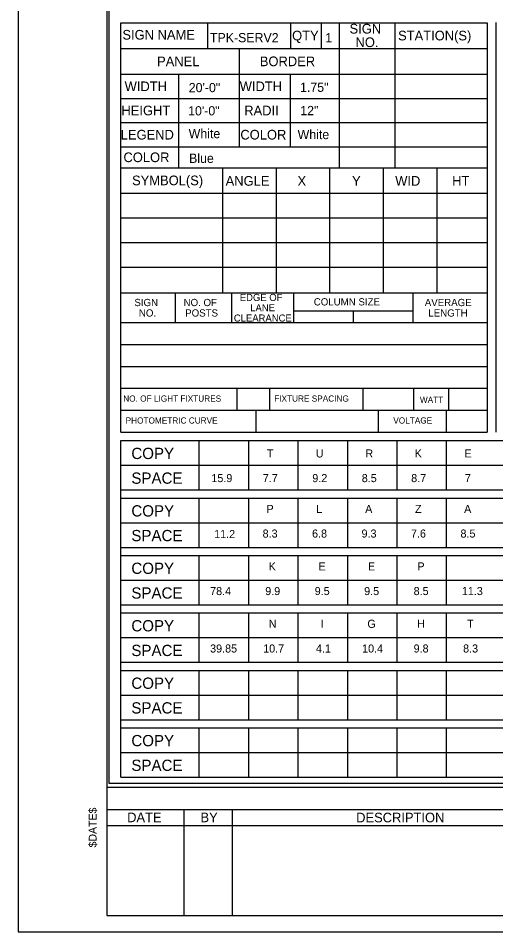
# Model space of a CAD drawing. Extents: x 17890071 to 17890754, y 17897628 to 17897992.
# Drawn here: x 17890071.1 to 17890100.2, y 17897766.7 to 17897822.3 of the extents above; entities that cross this region are included whole.
import ezdxf

# ---------------------------------------------------------------- set-up
doc = ezdxf.new("R2010")
doc.units = 0
for name, color, linetype in [('GSSign', 7, 'Continuous'), ('PlotBorder_dp', 7, 'Continuous'), ('SheetBorder_dp', 7, 'Continuous'), ('SheetLines_dp', 7, 'Continuous'), ('SheetLinesMisc1_dp', 7, 'Continuous'), ('SheetLinesMisc2_dp', 7, 'Continuous'), ('TextMinor', 7, 'Continuous'), ('TextMisc', 7, 'Continuous')]:
    doc.layers.add(name, color=color, linetype=linetype)

msp = doc.modelspace()

# ---------------------------------------------------------------- linework, layer by layer
at = {"layer": 'PlotBorder_dp'}
msp.add_lwpolyline([(17890071.13, 17897766.734), (17890232.646, 17897766.734), (17890232.646, 17897870.495), (17890071.13, 17897870.495)], close=True, dxfattribs=at)
at = {"layer": 'SheetBorder_dp'}
for p, q in [((17890076.514, 17897869.516), (17890076.514, 17897767.712)), ((17890076.514, 17897775.543), (17890227.262, 17897775.543)), ((17890076.514, 17897767.712), (17890227.262, 17897767.712))]:
    msp.add_line(p, q, dxfattribs=at)
at = {"layer": 'SheetLines_dp'}
for p, q in [((17890076.514, 17897774.173), (17890132.897, 17897774.173)), ((17890081.212, 17897774.173), (17890081.212, 17897767.712)), ((17890084.149, 17897774.173), (17890084.149, 17897767.712)), ((17890076.514, 17897773.194), (17890132.897, 17897773.194))]:
    msp.add_line(p, q, dxfattribs=at)
at = {"layer": 'SheetLinesMisc1_dp'}
for p, q in [((17890082.658, 17897820.501), (17890082.658, 17897822.069)), ((17890087.705, 17897822.069), (17890087.705, 17897820.501)), ((17890089.558, 17897822.069), (17890089.558, 17897820.501)), ((17890090.662, 17897822.069), (17890090.662, 17897813.235)), ((17890094.057, 17897822.069), (17890094.057, 17897813.235)), ((17890077.364, 17897820.501), (17890099.675, 17897820.501)), ((17890084.575, 17897820.501), (17890084.575, 17897814.499)), ((17890077.364, 17897818.932), (17890099.675, 17897818.932)), ((17890080.89, 17897818.932), (17890080.89, 17897813.235)), ((17890087.686, 17897818.917), (17890087.686, 17897814.499)), ((17890077.364, 17897817.46), (17890099.675, 17897817.46)), ((17890077.364, 17897815.988), (17890099.675, 17897815.988)), ((17890077.364, 17897814.515), (17890099.675, 17897814.515)), ((17890077.364, 17897813.235), (17890099.675, 17897813.235)), ((17890083.56, 17897813.235), (17890083.56, 17897805.616)), ((17890086.82, 17897813.235), (17890086.82, 17897805.616)), ((17890090.08, 17897813.235), (17890090.08, 17897805.616)), ((17890093.34, 17897813.206), (17890093.34, 17897805.616)), ((17890096.6, 17897813.206), (17890096.6, 17897805.616)), ((17890077.369, 17897811.702), (17890099.675, 17897811.702)), ((17890077.369, 17897810.199), (17890099.675, 17897810.199)), ((17890077.369, 17897808.695), (17890099.675, 17897808.695)), ((17890077.369, 17897807.192), (17890099.675, 17897807.192)), ((17890077.364, 17897805.616), (17890099.675, 17897805.616)), ((17890080.675, 17897805.616), (17890080.675, 17897803.819)), ((17890084.097, 17897805.616), (17890084.097, 17897803.819)), ((17890087.875, 17897805.616), (17890087.875, 17897803.819)), ((17890095.151, 17897805.616), (17890095.151, 17897803.819)), ((17890087.875, 17897804.538), (17890095.146, 17897804.538)), ((17890091.511, 17897804.538), (17890091.511, 17897803.819)), ((17890077.364, 17897803.819), (17890099.675, 17897803.819)), ((17890077.364, 17897802.484), (17890099.675, 17897802.484)), ((17890077.364, 17897801.148), (17890099.675, 17897801.148)), ((17890077.364, 17897799.813), (17890099.675, 17897799.813)), ((17890077.364, 17897798.477), (17890099.675, 17897798.477))]:
    msp.add_line(p, q, dxfattribs=at)
at = {"layer": 'SheetLinesMisc2_dp'}
for p, q in [((17890076.643, 17897869.435), (17890076.643, 17897775.777)), ((17890077.364, 17897797.141), (17890077.364, 17897822.069)), ((17890077.364, 17897822.069), (17890099.675, 17897822.069)), ((17890099.675, 17897822.069), (17890099.675, 17897797.141)), ((17890100.188, 17897822.071), (17890100.188, 17897797.179)), ((17890077.364, 17897799.812), (17890099.67, 17897799.812)), ((17890084.422, 17897799.812), (17890084.422, 17897798.477)), ((17890086.415, 17897799.812), (17890086.415, 17897798.477)), ((17890092.09, 17897799.812), (17890092.09, 17897798.477)), ((17890095.177, 17897799.812), (17890095.177, 17897798.477)), ((17890097.306, 17897799.812), (17890097.306, 17897798.477)), ((17890077.364, 17897798.477), (17890099.67, 17897798.477)), ((17890085.592, 17897798.477), (17890085.592, 17897797.141)), ((17890093.035, 17897798.477), (17890093.035, 17897797.141)), ((17890097.177, 17897798.477), (17890097.177, 17897797.141)), ((17890077.364, 17897797.141), (17890099.67, 17897797.141)), ((17890077.364, 17897797.141), (17890099.675, 17897797.141)), ((17890100.188, 17897797.179), (17890100.188, 17897797.146)), ((17890077.364, 17897796.631), (17890151.359, 17897796.631)), ((17890077.364, 17897776.142), (17890077.364, 17897796.631)), ((17890082.127, 17897796.631), (17890082.127, 17897793.624)), ((17890085.138, 17897796.631), (17890085.138, 17897793.624)), ((17890088.148, 17897796.631), (17890088.148, 17897793.624)), ((17890091.158, 17897796.631), (17890091.158, 17897793.624)), ((17890094.168, 17897796.631), (17890094.168, 17897793.624)), ((17890097.177, 17897796.631), (17890097.177, 17897793.624)), ((17890077.364, 17897795.129), (17890151.359, 17897795.129)), ((17890077.364, 17897793.624), (17890151.359, 17897793.624)), ((17890077.364, 17897793.134), (17890151.359, 17897793.134)), ((17890082.127, 17897793.134), (17890082.127, 17897790.128)), ((17890085.138, 17897793.134), (17890085.138, 17897790.128)), ((17890088.148, 17897793.134), (17890088.148, 17897790.128)), ((17890091.158, 17897793.134), (17890091.158, 17897790.128)), ((17890094.168, 17897793.134), (17890094.168, 17897790.128)), ((17890097.177, 17897793.134), (17890097.177, 17897790.128)), ((17890077.364, 17897791.631), (17890151.359, 17897791.631)), ((17890077.364, 17897790.128), (17890151.359, 17897790.128)), ((17890077.364, 17897789.637), (17890151.359, 17897789.637)), ((17890082.127, 17897789.637), (17890082.127, 17897786.631)), ((17890085.138, 17897789.637), (17890085.138, 17897786.631)), ((17890088.148, 17897789.637), (17890088.148, 17897786.631)), ((17890091.158, 17897789.637), (17890091.158, 17897786.631)), ((17890094.168, 17897789.637), (17890094.168, 17897786.631)), ((17890097.177, 17897789.637), (17890097.177, 17897786.631)), ((17890077.364, 17897788.135), (17890151.359, 17897788.135)), ((17890077.364, 17897786.631), (17890151.359, 17897786.631)), ((17890077.364, 17897786.141), (17890151.359, 17897786.141)), ((17890082.127, 17897786.141), (17890082.127, 17897783.135)), ((17890085.138, 17897786.141), (17890085.138, 17897783.135)), ((17890088.148, 17897786.141), (17890088.148, 17897783.135)), ((17890091.158, 17897786.141), (17890091.158, 17897783.135)), ((17890094.168, 17897786.141), (17890094.168, 17897783.135)), ((17890097.177, 17897786.141), (17890097.177, 17897783.135)), ((17890077.364, 17897784.639), (17890151.359, 17897784.639)), ((17890077.364, 17897783.135), (17890151.359, 17897783.135)), ((17890077.364, 17897782.644), (17890151.359, 17897782.644)), ((17890082.127, 17897782.644), (17890082.127, 17897779.638)), ((17890085.138, 17897782.644), (17890085.138, 17897779.638)), ((17890088.148, 17897782.644), (17890088.148, 17897779.638)), ((17890091.158, 17897782.644), (17890091.158, 17897779.638)), ((17890094.168, 17897782.644), (17890094.168, 17897779.638)), ((17890097.177, 17897782.644), (17890097.177, 17897779.638)), ((17890077.364, 17897781.141), (17890151.359, 17897781.141)), ((17890077.364, 17897779.638), (17890151.359, 17897779.638)), ((17890077.364, 17897779.148), (17890151.359, 17897779.148)), ((17890082.127, 17897779.148), (17890082.127, 17897776.142)), ((17890085.138, 17897779.148), (17890085.138, 17897776.142)), ((17890088.148, 17897779.148), (17890088.148, 17897776.142)), ((17890091.158, 17897779.148), (17890091.158, 17897776.142)), ((17890094.168, 17897779.148), (17890094.168, 17897776.142)), ((17890097.177, 17897779.148), (17890097.177, 17897776.142)), ((17890077.364, 17897777.645), (17890151.359, 17897777.645)), ((17890077.364, 17897776.142), (17890151.359, 17897776.142)), ((17890076.643, 17897775.777), (17890227.099, 17897775.777))]:
    msp.add_line(p, q, dxfattribs=at)

# ---------------------------------------------------------------- texts
at = {"layer": 'GSSign'}
for s, height, p in [('TPK-SERV2', 0.5624, (17890082.795, 17897820.878)), ('1', 0.562, (17890089.815, 17897820.877)), ('20\'-0"', 0.5624, (17890081.506, 17897817.838)), ('1.75"', 0.5624, (17890088.279, 17897817.859)), ('10\'-0"', 0.5624, (17890081.468, 17897816.425)), ('12"', 0.5624, (17890088.293, 17897816.44)), ('White', 0.5624, (17890081.5, 17897815.038)), ('White', 0.5624, (17890088.131, 17897814.983)), ('Blue', 0.5624, (17890081.525, 17897813.534)), ('T', 0.49, (17890086.26, 17897795.604)), ('U', 0.49, (17890089.239, 17897795.604)), ('R', 0.49, (17890092.256, 17897795.604)), ('K', 0.49, (17890095.255, 17897795.604)), ('E', 0.49, (17890098.289, 17897795.604)), ('15.9', 0.4902, (17890082.881, 17897794.102)), ('7.7', 0.4902, (17890086.013, 17897794.102)), ('9.2', 0.4902, (17890089.025, 17897794.102)), ('8.5', 0.4902, (17890092.036, 17897794.102)), ('8.7', 0.4902, (17890095.044, 17897794.102)), ('7', 0.49, (17890098.311, 17897794.102)), ('P', 0.49, (17890086.238, 17897792.225)), ('L', 0.49, (17890089.265, 17897792.225)), ('A', 0.49, (17890092.242, 17897792.225)), ('Z', 0.49, (17890095.275, 17897792.225)), ('A', 0.49, (17890098.263, 17897792.225)), ('11.2', 0.4902, (17890083.052, 17897790.698)), ('8.3', 0.4902, (17890086.001, 17897790.727)), ('6.8', 0.4902, (17890089.01, 17897790.727)), ('9.3', 0.4902, (17890092.022, 17897790.727)), ('7.6', 0.4902, (17890095.03, 17897790.727)), ('8.5', 0.4902, (17890098.043, 17897790.727)), ('K', 0.49, (17890086.369, 17897788.729)), ('E', 0.49, (17890089.403, 17897788.729)), ('E', 0.49, (17890092.413, 17897788.729)), ('P', 0.49, (17890095.422, 17897788.729)), ('78.4', 0.4902, (17890082.806, 17897787.226)), ('9.9', 0.4902, (17890086.16, 17897787.226)), ('9.5', 0.4902, (17890089.171, 17897787.226)), ('9.5', 0.4902, (17890092.181, 17897787.226)), ('8.5', 0.4902, (17890095.192, 17897787.226)), ('11.3', 0.4902, (17890098.126, 17897787.226)), ('N', 0.49, (17890086.373, 17897785.233)), ('I', 0.49, (17890089.535, 17897785.233)), ('G', 0.49, (17890092.375, 17897785.233)), ('H', 0.49, (17890095.404, 17897785.233)), ('T', 0.49, (17890098.447, 17897785.233)), ('39.85', 0.4902, (17890082.806, 17897783.73)), ('10.7', 0.4902, (17890086.035, 17897783.73)), ('4.1', 0.4902, (17890089.245, 17897783.73)), ('10.4', 0.4902, (17890092.055, 17897783.73)), ('9.8', 0.4902, (17890095.19, 17897783.73)), ('8.3', 0.4902, (17890098.202, 17897783.73))]:
    msp.add_text(s, height=height, dxfattribs=at).set_placement(p)
at = {"layer": 'TextMinor'}
for s, height, p in [('SIGN', 0.5882, (17890091.292, 17897821.408)), ('SIGN NAME', 0.5882, (17890077.468, 17897821.04)), ('QTY', 0.5882, (17890087.796, 17897820.991)), ('STATION(S)', 0.5882, (17890094.246, 17897820.991)), ('NO.', 0.5882, (17890091.656, 17897820.585)), ('PANEL', 0.5882, (17890079.578, 17897819.422)), ('BORDER', 0.5882, (17890085.831, 17897819.422)), ('WIDTH', 0.5882, (17890077.604, 17897817.902)), ('WIDTH', 0.5882, (17890084.608, 17897817.902)), ('HEIGHT', 0.5882, (17890077.408, 17897816.43)), ('RADII', 0.5882, (17890084.883, 17897816.43)), ('LEGEND', 0.5882, (17890077.366, 17897814.957)), ('COLOR', 0.5882, (17890084.648, 17897814.957)), ('COLOR', 0.5882, (17890077.533, 17897813.581)), ('SYMBOL(S)', 0.5882, (17890078.054, 17897812.174)), ('ANGLE', 0.5882, (17890083.75, 17897812.145)), ('X', 0.588, (17890088.125, 17897812.145)), ('Y', 0.588, (17890091.445, 17897812.145)), ('WID', 0.5882, (17890094.072, 17897812.145)), ('HT', 0.5882, (17890097.538, 17897812.145)), ('SIGN', 0.4411, (17890078.197, 17897804.816)), ('NO. OF', 0.4411, (17890081.19, 17897804.816)), ('EDGE OF', 0.4313, (17890084.612, 17897805.129)), ('COLUMN SIZE', 0.44113, (17890089.113, 17897804.857)), ('AVERAGE', 0.4411, (17890095.871, 17897804.816)), ('LANE', 0.4313, (17890085.245, 17897804.502)), ('NO.', 0.4411, (17890078.47, 17897804.179)), ('POSTS', 0.4411, (17890081.289, 17897804.179)), ('CLEARANCE', 0.4313, (17890084.249, 17897803.875)), ('LENGTH', 0.4411, (17890096.088, 17897804.179)), ('NO. OF LIGHT FIXTURES', 0.37485, (17890077.518, 17897799.002)), ('FIXTURE SPACING', 0.37485, (17890086.708, 17897799.002)), ('WATT', 0.3749, (17890095.574, 17897798.928)), ('PHOTOMETRIC CURVE', 0.37485, (17890077.665, 17897797.667)), ('VOLTAGE', 0.3749, (17890093.954, 17897797.667)), ('COPY', 0.6862, (17890078.013, 17897795.507)), ('SPACE', 0.6862, (17890078.013, 17897794.003)), ('COPY', 0.6862, (17890078.013, 17897792.009)), ('SPACE', 0.6862, (17890078.013, 17897790.506)), ('COPY', 0.6862, (17890078.013, 17897788.514)), ('SPACE', 0.6862, (17890078.013, 17897787.01)), ('COPY', 0.6862, (17890078.013, 17897785.016)), ('SPACE', 0.6862, (17890078.013, 17897783.514)), ('COPY', 0.6862, (17890078.013, 17897781.519)), ('SPACE', 0.6862, (17890078.013, 17897780.017)), ('COPY', 0.6862, (17890078.013, 17897778.023)), ('SPACE', 0.6862, (17890078.013, 17897776.521))]:
    msp.add_text(s, height=height, dxfattribs=at).set_placement(p)
msp.add_text('$DATE$', height=0.4797, rotation=90, dxfattribs=at).set_placement((17890075.897, 17897771.865))
at = {"layer": 'TextMisc'}
for s, height, rotation, p in [('DATE', 0.5873, 359.8693, (17890077.757, 17897773.4)), ('DESCRIPTION', 0.58721, 0.0498, (17890091.696, 17897773.39))]:
    msp.add_text(s, height=height, rotation=rotation, dxfattribs=at).set_placement(p)
msp.add_text('BY', height=0.5873, dxfattribs=at).set_placement((17890082.221, 17897773.4))

doc.saveas('drawing.dxf')
